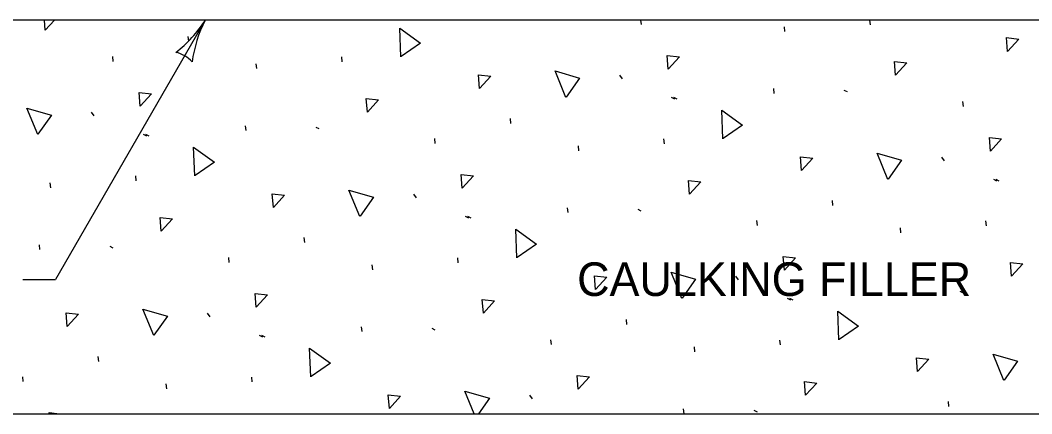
# Model space of a CAD drawing. Extents: x 49991.4 to 50021, y 49987.6 to 50011.4.
# Drawn here: x 50005.88 to 50007.688, y 49992.583 to 49993.286 of the extents above; entities that cross this region are included whole.
import ezdxf

# ---------------------------------------------------------------- set-up
doc = ezdxf.new("R2010")
doc.units = 0
for name, color, linetype in [('Level 1', 7, 'Continuous'), ('Level 2', 7, 'Continuous'), ('Level 3', 7, 'Continuous'), ('Level 4', 7, 'Continuous')]:
    doc.layers.add(name, color=color, linetype=linetype)

msp = doc.modelspace()

# ---------------------------------------------------------------- linework, layer by layer
at = {"layer": 'Level 1'}
msp.add_line((50011.4513, 49993.2857), (50004.6259, 49993.2857), dxfattribs=at)
msp.add_lwpolyline([(50001.9803, 49992.5827), (50004.606, 49992.5827), (50014.3713, 49992.5827)], dxfattribs=at)
at = {"layer": 'Level 3'}
for p in [(50006.2103, 49993.2857), (50005.884, 49992.8225)]:
    msp.add_line(p, (50005.9429, 49992.8225), dxfattribs=at)
for centre, radius, start, end in [((50006.0225, 49993.4047), 0.2223, 307.456, 327.6395), ((50006.4176, 49993.1793), 0.233, 152.8273, 172.0772), ((50006.1462, 49993.1747), 0.0548, 42.1388, 77.8612)]:
    msp.add_arc(centre, radius, start, end, dxfattribs=at)
at = {"layer": 'Level 4'}
for p, q in [((50006.9901, 49993.2783), (50006.9893, 49993.2857)), ((50007.3996, 49993.2777), (50007.3987, 49993.2857)), ((50007.2467, 49993.2654), (50007.2457, 49993.2741)), ((50006.181, 49993.2481), (50006.1801, 49993.2568)), ((50006.0459, 49993.2121), (50006.045, 49993.2208)), ((50006.4554, 49993.2115), (50006.4545, 49993.2202)), ((50006.3025, 49993.1993), (50006.3016, 49993.208)), ((50006.9508, 49993.1878), (50006.9556, 49993.1813)), ((50007.2275, 49993.1548), (50007.2266, 49993.1635)), ((50007.352, 49993.161), (50007.3578, 49993.1582)), ((50007.0436, 49993.1482), (50007.0494, 49993.1454)), ((50007.0477, 49993.1482), (50007.0535, 49993.1454)), ((50007.5659, 49993.1317), (50007.565, 49993.1404)), ((50006.0066, 49993.1216), (50006.0114, 49993.1152)), ((50006.7568, 49993.1015), (50006.7559, 49993.1102)), ((50006.2833, 49993.0886), (50006.2824, 49993.0973)), ((50006.4079, 49993.0949), (50006.4136, 49993.0921)), ((50006.0995, 49993.0821), (50006.1052, 49993.0792)), ((50006.1035, 49993.0821), (50006.1093, 49993.0792)), ((50006.6217, 49993.0656), (50006.6208, 49993.0743)), ((50007.0312, 49993.065), (50007.0302, 49993.0737)), ((50006.8783, 49993.0527), (50006.8774, 49993.0614)), ((50007.5266, 49993.0412), (50007.5313, 49993.0348)), ((50005.9341, 49992.9866), (50005.9332, 49992.9953)), ((50006.087, 49992.9989), (50006.0861, 49993.0076)), ((50007.6194, 49993.0016), (50007.6252, 49992.9988)), ((50007.6235, 49993.0017), (50007.6293, 49992.9988)), ((50006.5824, 49992.9751), (50006.5872, 49992.9686)), ((50007.3326, 49992.955), (50007.3317, 49992.9637)), ((50006.8591, 49992.9421), (50006.8582, 49992.9508)), ((50006.9837, 49992.9484), (50006.9894, 49992.9455)), ((50006.6752, 49992.9355), (50006.681, 49992.9327)), ((50006.6793, 49992.9355), (50006.6851, 49992.9327)), ((50007.1975, 49992.919), (50007.1966, 49992.9277)), ((50007.607, 49992.9184), (50007.606, 49992.9271)), ((50007.4541, 49992.9062), (50007.4532, 49992.9149)), ((50005.9149, 49992.8759), (50005.914, 49992.8846)), ((50006.3884, 49992.8888), (50006.3875, 49992.8975)), ((50006.0395, 49992.8822), (50006.0452, 49992.8794)), ((50006.2533, 49992.8529), (50006.2524, 49992.8616)), ((50006.5099, 49992.84), (50006.509, 49992.8487)), ((50006.6628, 49992.8523), (50006.6619, 49992.861)), ((50007.1582, 49992.8285), (50007.163, 49992.8221)), ((50007.4349, 49992.7955), (50007.434, 49992.8042)), ((50007.5595, 49992.8018), (50007.5652, 49992.799)), ((50007.251, 49992.789), (50007.2568, 49992.7861)), ((50007.2551, 49992.789), (50007.2609, 49992.7861)), ((50006.214, 49992.7624), (50006.2188, 49992.7559)), ((50006.9642, 49992.7423), (50006.9633, 49992.751)), ((50006.3069, 49992.7228), (50006.3126, 49992.72)), ((50006.311, 49992.7228), (50006.3167, 49992.72)), ((50006.4907, 49992.7294), (50006.4898, 49992.7381)), ((50006.6153, 49992.7357), (50006.621, 49992.7328)), ((50006.8291, 49992.7063), (50006.8282, 49992.715)), ((50007.2386, 49992.7057), (50007.2377, 49992.7144)), ((50007.0857, 49992.6935), (50007.0848, 49992.7022)), ((50006.02, 49992.6762), (50006.0191, 49992.6849)), ((50005.8849, 49992.6402), (50005.884, 49992.6489)), ((50006.1415, 49992.6274), (50006.1406, 49992.6361)), ((50006.2944, 49992.6396), (50006.2935, 49992.6483)), ((50006.7898, 49992.6159), (50006.7946, 49992.6094)), ((50007.54, 49992.5957), (50007.5391, 49992.6044)), ((50007.0665, 49992.5828), (50007.0656, 49992.5915)), ((50007.1911, 49992.5891), (50007.1968, 49992.5863))]:
    msp.add_line(p, q, dxfattribs=at)
for points in [[(50005.9244, 49993.2681), (50005.923, 49993.2857)], [(50005.9406, 49993.2857), (50005.9244, 49993.2681)], [(50006.5599, 49993.2206), (50006.558, 49993.2718), (50006.595, 49993.245), (50006.5606, 49993.2211)], [(50007.6447, 49993.23), (50007.6428, 49993.2546), (50007.6648, 49993.2519), (50007.6447, 49993.23)], [(50007.0382, 49993.1984), (50007.0364, 49993.223), (50007.0584, 49993.2203), (50007.0382, 49993.1984)], [(50007.4443, 49993.1877), (50007.4425, 49993.2122), (50007.4645, 49993.2096), (50007.4443, 49993.1877)], [(50006.855, 49993.1476), (50006.8357, 49993.1951), (50006.8796, 49993.1825), (50006.8555, 49993.1483)], [(50006.7005, 49993.1639), (50006.6986, 49993.1884), (50006.7207, 49993.1858), (50006.7005, 49993.1639)], [(50006.0941, 49993.1323), (50006.0922, 49993.1568), (50006.1142, 49993.1542), (50006.0941, 49993.1323)], [(50006.5002, 49993.1215), (50006.4983, 49993.1461), (50006.5203, 49993.1434), (50006.5002, 49993.1215)], [(50005.9108, 49993.0815), (50005.8915, 49993.1289), (50005.9355, 49993.1164), (50005.9113, 49993.0821)], [(50007.1357, 49993.0741), (50007.1338, 49993.1253), (50007.1708, 49993.0984), (50007.1364, 49993.0745)], [(50007.614, 49993.0519), (50007.6122, 49993.0764), (50007.6342, 49993.0737), (50007.614, 49993.0519)], [(50006.1915, 49993.0079), (50006.1896, 49993.0591), (50006.2266, 49993.0323), (50006.1923, 49993.0084)], [(50007.4307, 49993.001), (50007.4115, 49993.0485), (50007.4554, 49993.036), (50007.4313, 49993.0017)], [(50007.2763, 49993.0173), (50007.2744, 49993.0419), (50007.2964, 49993.0392), (50007.2763, 49993.0173)], [(50006.6699, 49992.9857), (50006.668, 49993.0103), (50006.69, 49993.0076), (50006.6699, 49992.9857)], [(50007.076, 49992.975), (50007.0741, 49992.9995), (50007.0961, 49992.9969), (50007.076, 49992.975)], [(50006.3321, 49992.9512), (50006.3302, 49992.9758), (50006.3523, 49992.9731), (50006.3321, 49992.9512)], [(50006.4866, 49992.9349), (50006.4673, 49992.9824), (50006.5112, 49992.9698), (50006.4871, 49992.9356)], [(50006.1318, 49992.9088), (50006.1299, 49992.9334), (50006.1519, 49992.9307), (50006.1318, 49992.9088)], [(50006.7673, 49992.8614), (50006.7654, 49992.9126), (50006.8024, 49992.8858), (50006.7681, 49992.8618)], [(50007.2457, 49992.8392), (50007.2438, 49992.8637), (50007.2658, 49992.8611), (50007.2457, 49992.8392)], [(50007.6518, 49992.8284), (50007.6499, 49992.853), (50007.6719, 49992.8503), (50007.6518, 49992.8284)], [(50007.0624, 49992.7884), (50007.0431, 49992.8358), (50007.087, 49992.8233), (50007.0629, 49992.789)], [(50006.9079, 49992.8047), (50006.906, 49992.8292), (50006.9281, 49992.8265), (50006.9079, 49992.8047)], [(50006.3015, 49992.773), (50006.2996, 49992.7976), (50006.3216, 49992.7949), (50006.3015, 49992.773)], [(50006.7076, 49992.7623), (50006.7057, 49992.7868), (50006.7277, 49992.7842), (50006.7076, 49992.7623)], [(50005.9637, 49992.7385), (50005.9618, 49992.7631), (50005.9839, 49992.7604), (50005.9637, 49992.7385)], [(50006.1182, 49992.7222), (50006.0989, 49992.7697), (50006.1429, 49992.7572), (50006.1187, 49992.7229)], [(50007.3431, 49992.7148), (50007.3412, 49992.766), (50007.3782, 49992.7392), (50007.3438, 49992.7153)], [(50006.3989, 49992.6487), (50006.397, 49992.6999), (50006.434, 49992.6731), (50006.3997, 49992.6491)], [(50007.6382, 49992.6418), (50007.6189, 49992.6893), (50007.6628, 49992.6767), (50007.6387, 49992.6425)], [(50007.4837, 49992.6581), (50007.4818, 49992.6827), (50007.5039, 49992.68), (50007.4837, 49992.6581)], [(50006.8773, 49992.6265), (50006.8754, 49992.651), (50006.8974, 49992.6484), (50006.8773, 49992.6265)], [(50007.2834, 49992.6157), (50007.2815, 49992.6403), (50007.3035, 49992.6376), (50007.2834, 49992.6157)], [(50006.5395, 49992.592), (50006.5376, 49992.6165), (50006.5597, 49992.6139), (50006.5395, 49992.592)], [(50006.6911, 49992.5827), (50006.6747, 49992.6231), (50006.7187, 49992.6106), (50006.699, 49992.5827)], [(50005.9314, 49992.5827), (50005.9312, 49992.5849), (50005.9497, 49992.5827)]]:
    msp.add_lwpolyline(points, dxfattribs=at)

# ---------------------------------------------------------------- texts
at = {"layer": 'Level 2'}
msp.add_text('CAULKING FILLER', height=0.06, dxfattribs=at).set_placement((50006.8752, 49992.7931))

doc.saveas('drawing.dxf')
